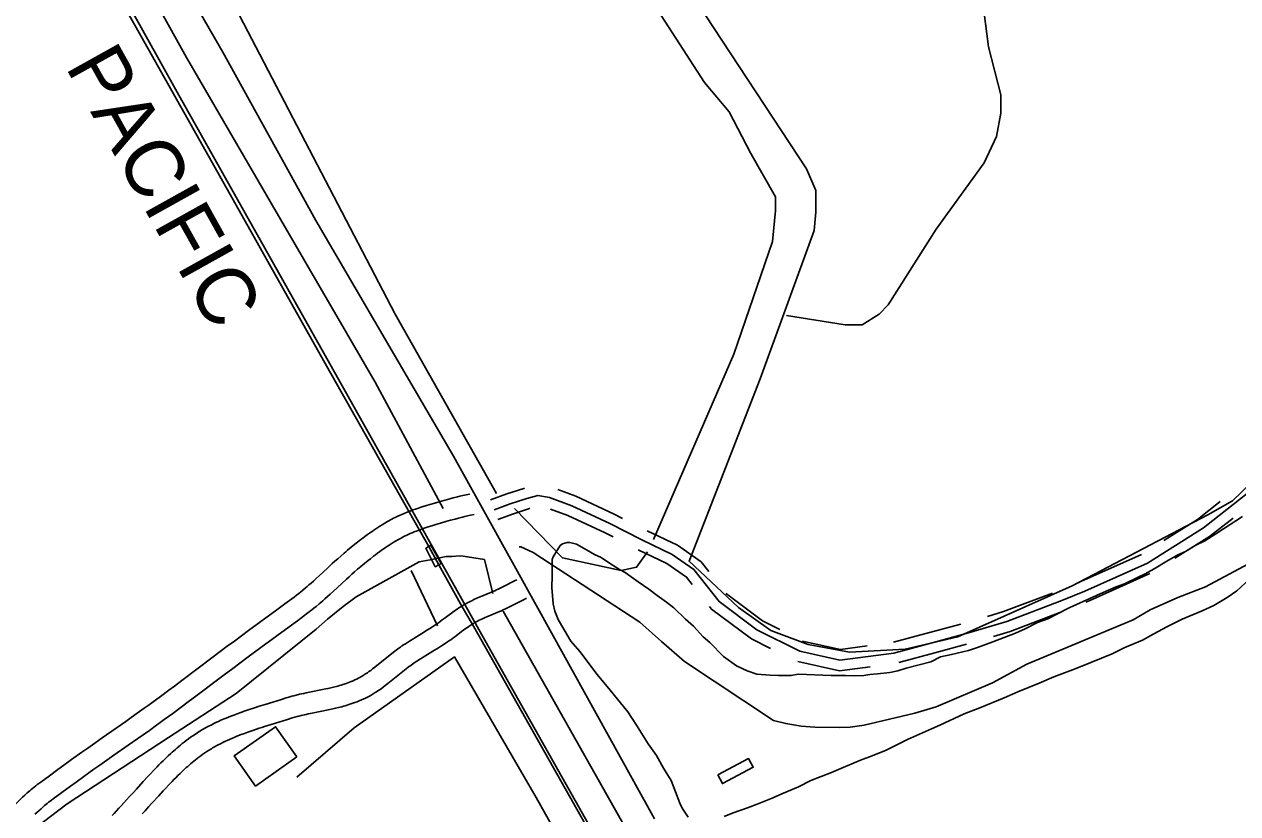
# Model space of a CAD drawing. Extents: x 3161514 to 3199414, y 831166 to 856601.
# Drawn here: x 3181850 to 3183589, y 843007 to 844138 of the extents above; entities that cross this region are included whole.
import ezdxf

# ---------------------------------------------------------------- set-up
doc = ezdxf.new("R2010")
doc.units = 0
for name, color, linetype in [('V-BLDG-OTLN', 7, 'Continuous'), ('V-BRDG-OTLN', 7, 'Continuous'), ('V-RAIL-IDEN', 7, 'Continuous'), ('V-RAIL-TRAK', 7, 'Continuous'), ('V-ROAD-CNTR', 7, 'Continuous'), ('V-SITE-VEGE', 7, 'Continuous'), ('V-TOPO-SHOR', 7, 'Continuous')]:
    doc.layers.add(name, color=color, linetype=linetype)

msp = doc.modelspace()

# ---------------------------------------------------------------- linework, layer by layer
at = {"layer": 'V-BLDG-OTLN'}
for points in [[(3182240.7, 843088.3), (3182181.5, 843046.2), (3182150.9, 843089.3), (3182210.2, 843131.3)], [(3182844.1, 843062.1), (3182888.3, 843085.6), (3182894.8, 843073.2), (3182850.7, 843049.7)]]:
    msp.add_lwpolyline(points, close=True, dxfattribs=at)
at = {"layer": 'V-BRDG-OTLN'}
msp.add_lwpolyline([(3182444.4, 843363.4), (3182439.2, 843360.5), (3182425.7, 843387), (3182429.8, 843389.6), (3182432.9, 843391.7), (3182447.8, 843365.4)], close=True, dxfattribs=at)
at = {"layer": 'V-RAIL-TRAK'}
msp.add_line((3182429.8, 843389.6), (3182444.4, 843363.4), dxfattribs=at)
for points in [[(3180808.7, 846265.6), (3180921.2, 846065.7), (3181051.5, 845834.5), (3181182.4, 845602.6), (3181298.1, 845396.9), (3181382.8, 845246.9), (3181460, 845109.8), (3181608.7, 844845.1), (3181772, 844555.9), (3181938.1, 844261.9), (3182098, 843978.3), (3182283.2, 843648.3), (3182416.6, 843413.2), (3182429.8, 843389.6)], [(3182444.4, 843363.4), (3182477.7, 843303.1), (3182494.1, 843275.3), (3182710.8, 842891.1), (3182875.1, 842600.8), (3182935.9, 842492.1), (3183049.4, 842291.7), (3183163.3, 842088.1), (3183340, 841765.1), (3183517.8, 841418.9), (3183619.3, 841219.9), (3183785.7, 840890.6), (3183936.6, 840594.7), (3184059.2, 840354.1)]]:
    msp.add_lwpolyline(points, dxfattribs=at)
at = {"layer": 'V-ROAD-CNTR'}
for points in [[(3181367.5, 845470.9), (3181582.7, 845085.2), (3181753.5, 844776), (3181904.3, 844497.6), (3182134.7, 844098.3), (3182267.9, 843856.9), (3182465.1, 843519.1), (3182588.4, 843297), (3182753.6, 842999.4)], [(3181321.6, 845380.8), (3181534.1, 844989.8), (3181799.8, 844524.4), (3182069.3, 844040.9), (3182292.1, 843643.9), (3182510, 843255.2), (3182750, 842829.8)], [(3182488.6, 843464.8), (3182483.3, 843463.6), (3182478.6, 843462.5), (3182474.5, 843461.6), (3182470.9, 843460.7), (3182464.7, 843459.1), (3182460.1, 843457.9), (3182453.3, 843456), (3182446.4, 843454.1), (3182438.4, 843451.8), (3182431.4, 843449.8), (3182425.2, 843447.9), (3182419.8, 843446.2), (3182415, 843444.7), (3182410.9, 843443.2), (3182407.2, 843441.9), (3182404.1, 843440.7), (3182401.3, 843439.7), (3182398.8, 843438.7), (3182394.6, 843437), (3182391.4, 843435.6), (3182389, 843434.5), (3182385.4, 843432.9), (3182381.9, 843431.2), (3182379.4, 843430), (3182377.1, 843428.8), (3182374.9, 843427.6), (3182372.8, 843426.4), (3182370.7, 843425.3), (3182366.8, 843423), (3182363.2, 843420.8), (3182359.8, 843418.7), (3182356.7, 843416.7), (3182353.8, 843414.8), (3182351.1, 843413), (3182348.7, 843411.3), (3182346.3, 843409.7), (3182342.1, 843406.6), (3182338.4, 843403.9), (3182335.2, 843401.5), (3182332.4, 843399.4), (3182327.6, 843395.6), (3182324, 843392.8), (3182318.8, 843388.5), (3182313.5, 843384.2), (3182310.9, 843382.1), (3182308.5, 843380), (3182303.8, 843375.9), (3182299.4, 843372.1), (3182295.4, 843368.5), (3182291.6, 843365.1), (3182284.7, 843358.7), (3182272.8, 843347.7), (3182268.4, 843343.6), (3182264.5, 843340.1), (3182261.1, 843337), (3182258.1, 843334.4), (3182255.5, 843332.1), (3182253.2, 843330.2), (3182249.1, 843326.8), (3182246.1, 843324.3), (3182243.8, 843322.4), (3182240.3, 843319.7), (3182236.8, 843317), (3182223.7, 843307.3), (3182212.1, 843298.8), (3182171.6, 843269), (3182151.3, 843254), (3182141.1, 843246.5), (3182131, 843239), (3182118.7, 843229.8), (3182075.9, 843197.5), (3182065.2, 843189.5), (3182057.2, 843183.5), (3182045.1, 843174.5), (3182033, 843165.6), (3182027.4, 843161.5), (3182022.1, 843157.7), (3182012, 843150.5), (3182003.2, 843144.3), (3181995.5, 843138.8), (3181981.9, 843129.3), (3181961.5, 843115.1), (3181951.2, 843107.9), (3181941, 843100.7), (3181932.5, 843094.7), (3181917.8, 843084.1)], [(3182518.5, 843456.4), (3182541.6, 843464.9), (3182565.9, 843472.9), (3182567.1, 843473.2)], [(3183605.4, 843467.3), (3183540.5, 843416.1), (3183460, 843365.8), (3183370.3, 843325.4), (3183337, 843312), (3183258.4, 843282), (3183203.2, 843265.7), (3183151.5, 843251.7), (3183096.2, 843236.8), (3183019.1, 843226.8), (3182961.5, 843239.6), (3182900.2, 843270), (3182845.9, 843310.7), (3182809.7, 843356.8), (3182778.7, 843378.3), (3182735.2, 843399.1), (3182689.3, 843422.4), (3182635, 843447.7), (3182603.1, 843459.7), (3182586.2, 843462.7), (3182570.2, 843458.5), (3182546.6, 843450.7), (3182523.6, 843442.3)], [(3182614.9, 843471.3), (3182640.8, 843461.6), (3182695.8, 843435.9), (3182707.7, 843429.9)], [(3182528.8, 843428.2), (3182551.5, 843436.5), (3182574.4, 843444.1), (3182574.7, 843444.2)], [(3183483.5, 843398.2), (3183531.8, 843428.4), (3183564.3, 843454)], [(3182494.9, 843435.4), (3182489.8, 843434.3), (3182485.4, 843433.3), (3182481.5, 843432.4), (3182478.2, 843431.6), (3182472.3, 843430.1), (3182467.9, 843428.9), (3182461.2, 843427.1), (3182454.5, 843425.2), (3182446.7, 843423), (3182439.9, 843421), (3182434, 843419.3), (3182429, 843417.7), (3182424.6, 843416.2), (3182420.8, 843414.9), (3182417.5, 843413.7), (3182414.6, 843412.7), (3182412.1, 843411.7), (3182410, 843410.9), (3182406.2, 843409.3), (3182403.4, 843408.1), (3182401.3, 843407.2), (3182398.2, 843405.8), (3182395.1, 843404.3), (3182393, 843403.2), (3182391, 843402.2), (3182389.1, 843401.2), (3182387.2, 843400.1), (3182385.5, 843399.2), (3182382, 843397.2), (3182378.8, 843395.2), (3182375.8, 843393.4), (3182373, 843391.6), (3182370.5, 843389.9), (3182368, 843388.3), (3182365.8, 843386.7), (3182363.7, 843385.2), (3182359.7, 843382.4), (3182356.3, 843379.9), (3182353.3, 843377.6), (3182350.8, 843375.6), (3182346.2, 843372.1), (3182342.8, 843369.4), (3182337.7, 843365.2), (3182332.6, 843361.1), (3182330.2, 843359.1), (3182327.9, 843357.1), (3182323.5, 843353.3), (3182319.4, 843349.7), (3182315.5, 843346.2), (3182311.9, 843342.9), (3182305.1, 843336.7), (3182293.1, 843325.6), (3182288.6, 843321.4), (3182284.5, 843317.8), (3182281, 843314.6), (3182277.8, 843311.8), (3182275.1, 843309.4), (3182272.6, 843307.3), (3182268.3, 843303.7), (3182265, 843301), (3182262.4, 843298.9), (3182258.6, 843296), (3182254.8, 843293), (3182241.5, 843283.2), (3182229.9, 843274.6), (3182189.3, 843244.8), (3182169.1, 843229.9), (3182159, 843222.4), (3182148.9, 843214.9), (3182136.7, 843205.8), (3182093.9, 843173.5), (3182083.2, 843165.5), (3182075.1, 843159.4), (3182062.9, 843150.4), (3182050.7, 843141.4), (3182045, 843137.2), (3182039.6, 843133.3), (3182029.4, 843126), (3182020.5, 843119.7), (3182012.7, 843114.3), (3181999.1, 843104.7), (3181978.6, 843090.5), (3181968.5, 843083.3), (3181958.3, 843076.2), (3181949.9, 843070.2), (3181935.2, 843059.7)], [(3182604.4, 843443.2), (3182629.2, 843433.9), (3182682.7, 843409), (3182694.1, 843403.2)], [(3183499.4, 843372.7), (3183549.1, 843403.8), (3183582.9, 843430.4)], [(3182743, 843411.9), (3182786.2, 843391.3), (3182820.2, 843367.8), (3182831.1, 843353.8)], [(3182730.1, 843384.9), (3182771.1, 843365.3), (3182799.3, 843345.7), (3182807.5, 843335.3)], [(3183360.5, 843337.6), (3183364.5, 843339.2), (3183451.2, 843378.3)], [(3182556, 843342), (3182552.8, 843340.2), (3182547, 843337.3), (3182542.7, 843335.1), (3182529.5, 843328.6), (3182526.8, 843327.3), (3182524.3, 843326.1), (3182521.8, 843325), (3182519.6, 843324), (3182501.2, 843316.3), (3182498.7, 843315.3), (3182494.6, 843313.4), (3182491.4, 843311.9), (3182489, 843310.7), (3182487.1, 843309.8), (3182484.5, 843308.4), (3182481.8, 843307), (3182480.1, 843306), (3182478.5, 843305.1), (3182475.6, 843303.3), (3182472.9, 843301.6), (3182470.4, 843299.9), (3182468.1, 843298.3), (3182466, 843296.8), (3182462.2, 843294), (3182458.9, 843291.6), (3182453.3, 843287.4), (3182449.2, 843284.3), (3182446.1, 843282.1), (3182443.9, 843280.4), (3182442.2, 843279.3), (3182439.7, 843277.5), (3182437.2, 843275.9), (3182432.2, 843272.7), (3182427.8, 843269.9), (3182420, 843265), (3182408.2, 843257.7), (3182402.2, 843254), (3182396.3, 843250.2), (3182393.8, 843248.6), (3182391.4, 843247), (3182389.1, 843245.4), (3182387, 843243.9), (3182384.9, 843242.3), (3182382.9, 843240.8), (3182379.1, 843237.9), (3182352.5, 843216.5), (3182349.4, 843214.1), (3182346.6, 843212), (3182344.1, 843210.2), (3182341.9, 843208.7), (3182340.1, 843207.5), (3182338.4, 843206.4), (3182337, 843205.5), (3182334.4, 843203.8), (3182332.5, 843202.7), (3182331, 843201.9), (3182328.8, 843200.7), (3182326.6, 843199.6), (3182325.3, 843198.9), (3182324, 843198.3), (3182321.3, 843197.1), (3182318.7, 843196), (3182316.2, 843195), (3182313.7, 843194), (3182311.2, 843193.2), (3182308.8, 843192.4), (3182306.5, 843191.6), (3182304.2, 843190.9), (3182301.9, 843190.3), (3182299.7, 843189.6), (3182297.6, 843189.1), (3182293.4, 843188), (3182289.4, 843187), (3182285.6, 843186.2), (3182282.1, 843185.4), (3182254.2, 843179.8), (3182250.6, 843179), (3182247.4, 843178.3), (3182244.7, 843177.7), (3182239.9, 843176.5), (3182236.2, 843175.6), (3182233.4, 843174.9), (3182229.3, 843173.7), (3182225.3, 843172.5), (3182218.6, 843170.4), (3182206.1, 843166.6)], [(3183371.7, 843309.8), (3183376.2, 843311.6), (3183463.5, 843350.9)], [(3182855.8, 843322.3), (3182856.4, 843321.5), (3182908.1, 843282.9), (3182932.9, 843270.5)], [(3183230.7, 843289.4), (3183253.6, 843296.2), (3183323.6, 843322.9)], [(3182570, 843315.4), (3182566.6, 843313.6), (3182560.6, 843310.6), (3182556.1, 843308.3), (3182542.7, 843301.6), (3182539.6, 843300.2), (3182536.7, 843298.8), (3182534, 843297.6), (3182531.4, 843296.4), (3182512.9, 843288.7), (3182510.8, 843287.8), (3182507, 843286.1), (3182504.3, 843284.8), (3182502.2, 843283.8), (3182500.8, 843283.1), (3182498.6, 843282), (3182496.4, 843280.8), (3182495.1, 843280.1), (3182494, 843279.4), (3182491.5, 843277.9), (3182489.3, 843276.5), (3182487.2, 843275.1), (3182485.3, 843273.7), (3182483.4, 843272.4), (3182479.9, 843269.9), (3182476.8, 843267.6), (3182471.3, 843263.4), (3182467.1, 843260.2), (3182463.8, 843257.8), (3182461.3, 843256), (3182459.4, 843254.7), (3182456.5, 843252.7), (3182453.5, 843250.7), (3182448.3, 843247.4), (3182443.8, 843244.5), (3182435.8, 843239.6), (3182424, 843232.2), (3182418.2, 843228.6), (3182412.5, 843225), (3182410.4, 843223.6), (3182408.3, 843222.2), (3182406.4, 843220.9), (3182404.5, 843219.5), (3182402.7, 843218.2), (3182401, 843216.9), (3182397.6, 843214.3), (3182371.1, 843193), (3182367.5, 843190.2), (3182364.3, 843187.8), (3182361.5, 843185.8), (3182359, 843184), (3182356.7, 843182.5), (3182354.8, 843181.2), (3182353, 843180.1), (3182349.9, 843178.2), (3182347.5, 843176.7), (3182345.6, 843175.7), (3182342.8, 843174.2), (3182340, 843172.7), (3182338.3, 843171.9), (3182336.6, 843171.1), (3182333.3, 843169.6), (3182330.1, 843168.2), (3182327, 843167), (3182324, 843165.9), (3182321, 843164.8), (3182318.2, 843163.9), (3182315.4, 843163), (3182312.7, 843162.2), (3182310.2, 843161.4), (3182307.7, 843160.7), (3182305.2, 843160), (3182300.5, 843158.9), (3182296.2, 843157.8), (3182292.1, 843156.9), (3182288.2, 843156.1), (3182260.3, 843150.4), (3182256.9, 843149.7), (3182254, 843149), (3182251.5, 843148.5), (3182247, 843147.4), (3182243.8, 843146.6), (3182241.4, 843145.9), (3182237.8, 843144.9), (3182234.1, 843143.8), (3182227.5, 843141.8), (3182214.9, 843137.9)], [(3182832.2, 843303.8), (3182835.3, 843299.8), (3182892.3, 843257.2), (3182919.6, 843243.6)], [(3183239.2, 843260.6), (3183263.2, 843267.8), (3183334.3, 843294.9)], [(3183096.1, 843252.3), (3183147.5, 843266.1), (3183192.6, 843278.3)], [(3182965.4, 843254), (3183019.8, 843242), (3183058.4, 843247)], [(3183103.8, 843223.3), (3183155.4, 843237.2), (3183200.4, 843249.4)], [(3182958.9, 843224.8), (3183018.4, 843211.5), (3183062.3, 843217.3)], [(3182206.1, 843166.6), (3182195.1, 843163.2), (3182185.5, 843160.2), (3182181.3, 843158.8), (3182177.3, 843157.5), (3182173.6, 843156.3), (3182166.6, 843153.9), (3182160.5, 843151.8), (3182155.1, 843149.8), (3182150.4, 843148), (3182146.3, 843146.5), (3182142.7, 843145), (3182139.6, 843143.7), (3182136.8, 843142.6), (3182132, 843140.5), (3182128.4, 843138.9), (3182125.7, 843137.6), (3182121.7, 843135.7), (3182117.7, 843133.7), (3182115.4, 843132.6), (3182113.1, 843131.4), (3182110.9, 843130.2), (3182108.8, 843129), (3182106.7, 843127.9), (3182104.7, 843126.7), (3182102.7, 843125.5), (3182100.8, 843124.3), (3182098.9, 843123.1), (3182095.3, 843120.8), (3182091.8, 843118.4), (3182088.5, 843116.1), (3182085.3, 843113.8), (3182082.3, 843111.6), (3182079.4, 843109.3), (3182076.6, 843107.1), (3182073.9, 843105), (3182071.4, 843102.9), (3182069, 843100.8), (3182066.6, 843098.8), (3182064.4, 843096.8), (3182062.2, 843094.9), (3182060.1, 843093), (3182056.2, 843089.4), (3182052.5, 843085.9), (3182049.1, 843082.5), (3182046, 843079.4), (3182043.1, 843076.5), (3182040.3, 843073.7), (3182035.3, 843068.4), (3182031, 843063.8), (3182027.2, 843059.7), (3182020.6, 843052.6), (3182010.8, 843041.9), (3182005.9, 843036.6), (3182001.1, 843031.3), (3181996.8, 843026.6), (3181992.7, 843022.3), (3181988.9, 843018.1), (3181985.4, 843014.3), (3181982.1, 843010.6), (3181979, 843007.1), (3181976.1, 843003.9)], [(3182214.9, 843137.9), (3182204, 843134.5), (3182194.6, 843131.6), (3182190.5, 843130.3), (3182186.6, 843129), (3182183.1, 843127.8), (3182176.4, 843125.6), (3182170.6, 843123.5), (3182165.5, 843121.7), (3182161.1, 843120), (3182157.3, 843118.5), (3182154, 843117.2), (3182151.1, 843116), (3182148.6, 843115), (3182144.1, 843113), (3182140.8, 843111.6), (3182138.4, 843110.4), (3182134.7, 843108.7), (3182131.1, 843106.9), (3182129.1, 843105.9), (3182127.2, 843104.9), (3182125.3, 843103.9), (3182123.5, 843102.9), (3182121.7, 843101.9), (3182120, 843100.8), (3182118.3, 843099.8), (3182116.6, 843098.8), (3182115, 843097.8), (3182111.8, 843095.7), (3182108.8, 843093.7), (3182105.8, 843091.7), (3182103, 843089.6), (3182100.4, 843087.6), (3182097.8, 843085.7), (3182095.3, 843083.7), (3182092.9, 843081.8), (3182090.7, 843079.9), (3182088.5, 843078), (3182086.3, 843076.2), (3182084.3, 843074.4), (3182082.3, 843072.6), (3182080.4, 843070.9), (3182076.8, 843067.5), (3182073.4, 843064.3), (3182070.2, 843061.2), (3182067.2, 843058.2), (3182064.5, 843055.4), (3182061.9, 843052.8), (3182057.1, 843047.8), (3182052.8, 843043.3), (3182049.2, 843039.3), (3182042.7, 843032.3), (3182033, 843021.7), (3182028, 843016.3), (3182023.1, 843010.9), (3182018.8, 843006.2)], [(3181917.7, 843084.1), (3181906.7, 843076.1), (3181898.4, 843070.1), (3181886, 843061.1), (3181873.7, 843052), (3181871.1, 843050.1), (3181868.7, 843048.3), (3181866.4, 843046.5), (3181864.2, 843044.7), (3181862, 843042.9), (3181860, 843041.2), (3181858, 843039.5), (3181854.2, 843036.3), (3181850.7, 843033.2), (3181847.5, 843030.2), (3181844.5, 843027.4), (3181841.8, 843024.7), (3181839.2, 843022.2), (3181836.8, 843019.9), (3181834.6, 843017.6), (3181830.5, 843013.4), (3181827, 843009.7), (3181823.9, 843006.4)], [(3181935.3, 843059.7), (3181924.3, 843051.8), (3181916.1, 843045.9), (3181903.8, 843036.9), (3181891.5, 843027.9), (3181889.2, 843026.2), (3181887.1, 843024.6), (3181885, 843022.9), (3181883, 843021.3), (3181881.1, 843019.8), (3181879.2, 843018.2), (3181877.5, 843016.8), (3181874.1, 843013.8), (3181870.9, 843010.9), (3181867.9, 843008.2), (3181865.2, 843005.7)]]:
    msp.add_lwpolyline(points, dxfattribs=at)
at = {"layer": 'V-SITE-VEGE'}
for points in [[(3183053.4, 843204.7), (3183062.2, 843206.3), (3183072.9, 843206.9), (3183090.5, 843209.1), (3183102.3, 843211.5), (3183114.1, 843215), (3183132.8, 843220.1), (3183149.4, 843224.3), (3183163.3, 843231.5), (3183179, 843234.8), (3183203.6, 843240.7), (3183216.4, 843245), (3183238.1, 843252.9), (3183270.6, 843265.3), (3183284.5, 843271.5), (3183302.3, 843280.6), (3183317.1, 843285.8), (3183329.1, 843292.2), (3183348.9, 843302.1), (3183396.4, 843323.6), (3183415.2, 843331.6), (3183427, 843336), (3183445.8, 843345), (3183456.7, 843350.4), (3183469.7, 843357.7), (3183487.6, 843368.7), (3183503.5, 843377.8), (3183514.4, 843382.2), (3183529.3, 843391.3), (3183542.2, 843397.6), (3183558.1, 843407.7), (3183569.1, 843415.1), (3183596.1, 843432.5)], [(3182801.4, 843001.6), (3182793.2, 843014.5), (3182789.6, 843021.5), (3182777.2, 843054), (3182766.3, 843072), (3182756.3, 843089.9), (3182744.3, 843106.9), (3182727.8, 843133.7), (3182715, 843152.7), (3182689.9, 843183.8), (3182671.3, 843206), (3182646.4, 843239), (3182633.3, 843254.1), (3182620.6, 843276), (3182615.1, 843285), (3182610.7, 843296.8), (3182608.2, 843307.6), (3182606.2, 843331), (3182606.8, 843347.5), (3182606.5, 843363.1), (3182606.8, 843370.8), (3182607.9, 843374.7), (3182618.2, 843390.8), (3182621.3, 843393.6), (3182628.1, 843395.3), (3182632, 843395.1), (3182641.7, 843392.8), (3182649.3, 843388.6), (3182661.6, 843381.3), (3182667.3, 843378.2), (3182676.9, 843373.9), (3182687.3, 843366.7), (3182703.4, 843356.4), (3182711.1, 843352.2), (3182723.4, 843343.9), (3182730, 843338.8), (3182745.1, 843328.5), (3182757.4, 843319.3), (3182770.7, 843310), (3182781, 843301.8), (3182797.9, 843285.6), (3182809.2, 843275.5), (3182823.2, 843260.3), (3182832.6, 843252.2), (3182852.2, 843232), (3182871.1, 843218.6), (3182886.4, 843211.2), (3182899.9, 843206.8), (3182919.2, 843205.1), (3182930.9, 843204.6), (3182949.4, 843204.9), (3182959.2, 843206.4), (3183006.7, 843204.6), (3183027.1, 843204.7), (3183039.8, 843204.3), (3183053.4, 843204.7)], [(3183606.2, 843342.7), (3183588, 843325.9), (3183574, 843316.7), (3183555.1, 843304.8), (3183538.3, 843297.6), (3183509.6, 843285.2), (3183487.8, 843274.3), (3183469, 843264.4), (3183453, 843255.3), (3183427.3, 843244.6), (3183409.5, 843235.6), (3183378.9, 843223.2), (3183356.2, 843214.3), (3183325.6, 843202.9), (3183304.8, 843193.9), (3183274.2, 843181.5), (3183254.4, 843172.6), (3183219.8, 843158.4), (3183197.1, 843149.5), (3183162.4, 843133.4), (3183150.6, 843128), (3183115.9, 843112.8), (3183085.2, 843097.5), (3183065.4, 843089.5), (3183048.7, 843083.3), (3183024, 843072.6), (3183007.1, 843065.5), (3182977.5, 843054), (3182959.7, 843045), (3182936, 843035.2), (3182922.1, 843029), (3182900.4, 843020.1), (3182886.6, 843014.8), (3182865.9, 843007.8), (3182853, 843002.5)]]:
    msp.add_lwpolyline(points, dxfattribs=at)
at = {"layer": 'V-TOPO-SHOR'}
for p, q in [((3182527, 843465.4), (3182381.5, 843722.4)), ((3182509.8, 843370.8), (3182509.6, 843370.8)), ((3182521.8, 843322.1), (3182509.8, 843370.8)), ((3182442.2, 843275.7), (3182404.6, 843355.4)), ((3182536.7, 843296.9), (3182946.5, 842570.1))]:
    msp.add_line(p, q, dxfattribs=at)
for points in [[(3180747.1, 846439.2), (3181094.5, 845843.4), (3181206.9, 845643.1), (3181430.8, 845255.8), (3181608.4, 844935.6), (3181889.3, 844435.7), (3181966, 844300.5), (3182082.8, 844090.3), (3182353.2, 843625.3), (3182450.6, 843444.1)], [(3182381.5, 843722.4), (3182158.4, 844150.9), (3181974.4, 844485.4), (3181851.2, 844710.1), (3181754.8, 844869.5), (3181561.4, 845213.7), (3181449.6, 845419.6), (3181361.3, 845566.2), (3181301.4, 845671.3), (3181184.1, 845886), (3181103.2, 846018.7), (3181077, 846068), (3180991, 846215.3)], [(3182942.4, 843720.5), (3183026.5, 843707.3), (3183050.8, 843707.3), (3183075.2, 843722.7), (3183088.4, 843736), (3183157.1, 843844.5), (3183225.7, 843939.6), (3183243.4, 843977.3), (3183250, 844010.5), (3183250, 844037), (3183232.3, 844105.6), (3183203.5, 844329.2), (3183183.6, 844481.9), (3183152.6, 844641.2), (3183128.3, 844723.1), (3183108.4, 844780.7), (3183095.1, 844811.6), (3183079.6, 844860.3), (3183075.2, 844933.4), (3183066.3, 845048.5), (3183061.9, 845154.7)], [(3182752, 843399.6), (3182867.1, 843665.2), (3182922.5, 843826.8), (3182926.9, 843871), (3182926.9, 843891), (3182891.5, 843952.9), (3182860.5, 844012.7), (3182825.1, 844054.7), (3182716.6, 844222.9), (3182630.3, 844298.2), (3182557.3, 844342.4), (3182488.7, 844371.2), (3182389.1, 844411.1), (3182293.9, 844422.1), (3182030.5, 844419.9), (3182015, 844424.3)], [(3182814, 844169.8), (3182971.1, 843930.8), (3182984.4, 843899.8), (3182984.4, 843868.8), (3182982.2, 843842.3), (3182904.8, 843629.8), (3182802.9, 843368.6), (3182873.8, 843302.2), (3182920.2, 843269), (3182973.4, 843249.1), (3183033.1, 843238.1), (3183112.8, 843242.5), (3183188, 843260.2), (3183351.8, 843333.2), (3183546.6, 843435), (3183582, 843455), (3183648.4, 843519.1)], [(3182552.9, 843443.9), (3182621.5, 843373.1), (3182705.6, 843355.4), (3182727.7, 843359.8), (3182743.2, 843381.9)], [(3182444.4, 843363.4), (3182439.2, 843360.5), (3182425.7, 843387), (3182429.8, 843389.6), (3182432.9, 843391.7), (3182447.8, 843365.4), (3182444.4, 843363.4)], [(3182509.6, 843370.8), (3182478.9, 843375.6), (3182473.7, 843376), (3182462.7, 843375.3), (3182455, 843375.4), (3182431.9, 843370.4), (3182416, 843367.6), (3182325.6, 843317.6), (3182307.3, 843303.5), (3182284.6, 843285.4), (3182268.2, 843271.3), (3182153.7, 843178.8), (3182056.7, 843115.9), (3181911.6, 843020.6), (3181865.9, 842986)], [(3183618, 843372), (3183543.3, 843331.6), (3183503.5, 843316.3), (3183464, 843298.9), (3183439.3, 843284.4), (3183287.1, 843221), (3183238, 843194.1), (3183157.2, 843159.7), (3183126.5, 843150.7), (3183053.7, 843133.6), (3183033.7, 843130.8), (3183019.2, 843130.1), (3182983.3, 843130.8), (3182963.8, 843132.2), (3182941.6, 843135.8), (3182923.8, 843140.1), (3182796.6, 843224.9), (3182763.2, 843253.5), (3182732.3, 843281), (3182579.4, 843381), (3182573.4, 843383.9), (3182561.6, 843389.1), (3182559.4, 843389.3)], [(3182871.6, 842516.6), (3182583.8, 843030), (3182466.5, 843231.4), (3182322.7, 843129.6), (3182240.8, 843058.8)]]:
    msp.add_lwpolyline(points, dxfattribs=at)

# ---------------------------------------------------------------- texts
at = {"layer": 'V-RAIL-IDEN'}
msp.add_text('PACIFIC', height=83, rotation=299.1241, dxfattribs=at).set_placement((3181908.1, 844077.7))

doc.saveas('drawing.dxf')
